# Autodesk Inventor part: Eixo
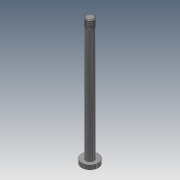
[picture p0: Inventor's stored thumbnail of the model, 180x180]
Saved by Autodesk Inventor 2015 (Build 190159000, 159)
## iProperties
Created: 2015-04
Part Number: Eixo
Material: Steel, Carbon
Document SubType Name: Modeling
Designer: TREINA6
Density: 7.85 g/cm^3
Appearance: Semi-Polished
Author: TREINA6
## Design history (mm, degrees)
sketch "Sketch1"
  geometry: C1 r 20 at (0, 0); 1 further point
  constraints: 1 centre point, 1 coincident
  dimensions: "d0" = 40 diameter of C1
extrude "Extrusion1" new body sketch "Sketch1" distance "d1" = 10; taper "d2" = 0 deg
sketch "Sketch2"
  geometry: C1 r 10 at (0, 0); 1 further point
  constraints: 1 centre point, 1 coincident
  dimensions: "d3" = 20 diameter of C1
extrude "Extrusion2" join sketch "Sketch2" distance "d4" = 300; taper "d5" = 0 deg
thread "Thread1" dims "d6" = 20, "d7" = 0
chamfer "Chamfer1" distance "d8" = 2; stored, may be unused: second distance "d9" = 2, angle "d10" = 45 deg
body "Solid1"
